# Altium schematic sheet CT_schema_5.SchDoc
size 245 x 200 mm
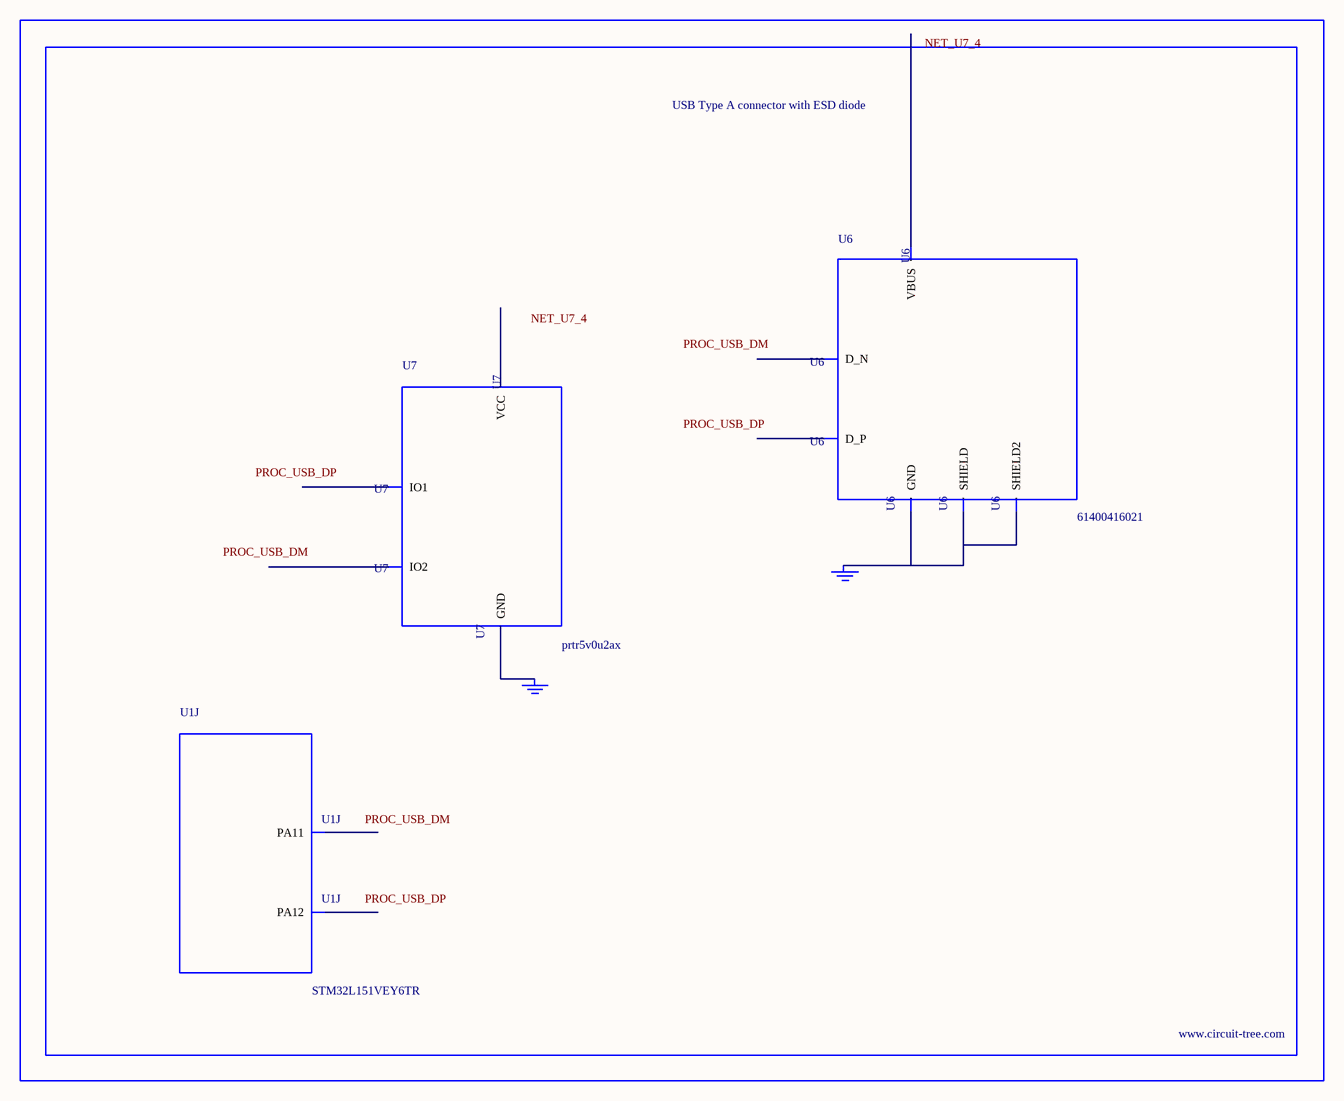
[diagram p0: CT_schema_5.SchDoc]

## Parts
BORDER4  (no value)
GND_INSTANCE_4_0  (no value)
GND_INSTANCE_4_1  (no value)
U1  STM32L151VEY6TR  [WLCSP104]  (part J of 10)
U6  61400416021  [USB-A-H]
U7  prtr5v0u2ax  [SOT143B]

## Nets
NetGND_INSTANCE_4_0_0: GND_INSTANCE_4_0.0(GND) U6.4(GND) U6.5(SHIELD) U6.6(SHIELD2)
NetGND_INSTANCE_4_1_0: GND_INSTANCE_4_1.0(GND) U7.1(GND)

Not connected (* = marked no-connect by the designer): U1 E1(PA11) E2(PA12); U6 1(VBUS) 2(D_N) 3(D_P); U7 2(IO1) 3(IO2) 4(VCC)

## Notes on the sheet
- Labels drawn without touching a wire or pin: NET_U7_4, PROC_USB_DM, PROC_USB_DP

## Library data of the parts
BORDER4 = BORDER_PAGE4
GND_INSTANCE_4_0 GND_INSTANCE_4_1 = GND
